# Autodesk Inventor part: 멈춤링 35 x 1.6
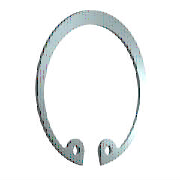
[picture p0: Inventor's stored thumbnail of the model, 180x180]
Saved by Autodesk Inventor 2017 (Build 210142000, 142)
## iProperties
IsCustomPart: 1
Created: 2012-02
Part Number: 멈춤링 35 x 1.6
Material: 강철, 연강
Description: 리테이닝 링(C형)
Document SubType Name: Modeling
Standard: KS B 1336
Designer: mduedu
Standards Organization: KS
Language: ko-KR
Size Designation: 35x1.6
Categories: <MemberInstance><Categories><Category DisplayName="샤프트 부품" InternalName="7f7aeb1f-a693-4053-b835-cee3144e0d98" Mnemonic="SHFT"><Category DisplayName="써클립" Inter
Density: 1 g/cm^3
Appearance: 파란색 - 벽 페인트 - 광택
Author: mduedu
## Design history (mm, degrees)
sketch "스케치1"
  geometry: L1 (0, 15.113)-(0, -73.177) reference; L2 (-45.5, 0)-(45.5, 0) reference; L3 (-4.964, 1)-(1.502, 1); L4 (0, -2.5)-(-5.307, -2.5); L5 (0, -17.5)-(-8.583, -33.888); L6 (-8.583, -33.888)-(-21.772, -26.981); L7 (-7.377, -31.585)-(-17.631, -26.214); L8 (-5.162, -32.745)-(-6.29, -34.898); L9 (5.162, -32.745)-(6.29, -34.898); C1 r 1.25 at (-7.377, -31.585); C2 r 1.25 at (7.377, -31.585); A1 r 15.875 centre (0, -18.375) between (11.82, -28.972) and (-11.82, -28.972); A2 r 18.5 centre (0, -17.5) between (6.29, -34.898) and (-6.29, -34.898); A3 r 2.5 centre (-7.377, -31.585) between (-5.162, -32.745) and (-8.668, -29.444); A4 r 2.5 centre (-9.959, -27.303) between (-11.82, -28.972) and (-8.668, -29.444); A5 r 2.5 centre (9.959, -27.303) between (8.668, -29.444) and (11.82, -28.972); A6 r 2.5 centre (7.377, -31.585) between (8.668, -29.444) and (5.162, -32.745); 3 further points
  constraints: 15 point on circle, 14 end point, 9 symmetric about line, 8 centre point, 6 tangent, 4 coincident, 4 point on line, 3 perpendicular, 1 parallel, 4 other
  dimensions: "d8" = 0.875 distance of A1.centre L5.start (= 0.25 x SRB1); "d38" = 3.5 distance between parallel lines of L4 L3 (= SRB1); "d39" = 17.5 distance from line of L5.start L2 (= 0.5 x WD); "d43" = 18.5 radius of A2 (= 0.5 x ND); "d45" = 2.6 distance between parallel lines of L7 L6 (= 0.5 x SRB2); "d46" = 2.5 radius of A4 (= SD5); "d47" = 6.29 distance from line of L1 L8.end (= 0.17 x ND); "d48" = 2.5 diameter of C1 (= SD5); "d49" = 2.5 radius of A3 (= SD5)
extrude "본체" new body sketch "스케치1" distance "d2" = 1.6 (= SD); taper "d3" = 0 deg
workaxis "Work Axis1"
workaxis "Work Axis2"
workplane "Work Plane1"
body "Solid1"
other parameters: "WD" = 35 [user parameter; used in 3 equation terms], "SD" = 1.6 [user parameter; used in 1 equation term], "SRB1" = 3.5 [user parameter; used in 2 equation terms], "ND" = 37 [user parameter; used in 2 equation terms], "SRB2" = 5.2 [user parameter; used in 1 equation term], "SD5" = 2.5 [user parameter; used in 3 equation terms], "d50" = 0, "d51" = 0, "d52" = 0, "d53" = 0, "WDMIN" = 34 [user parameter], "SD6" = 37.8 [user parameter], "WDMAX" = 35 (= WD) [user parameter], "NND" = 35 (= WD) [user parameter]
